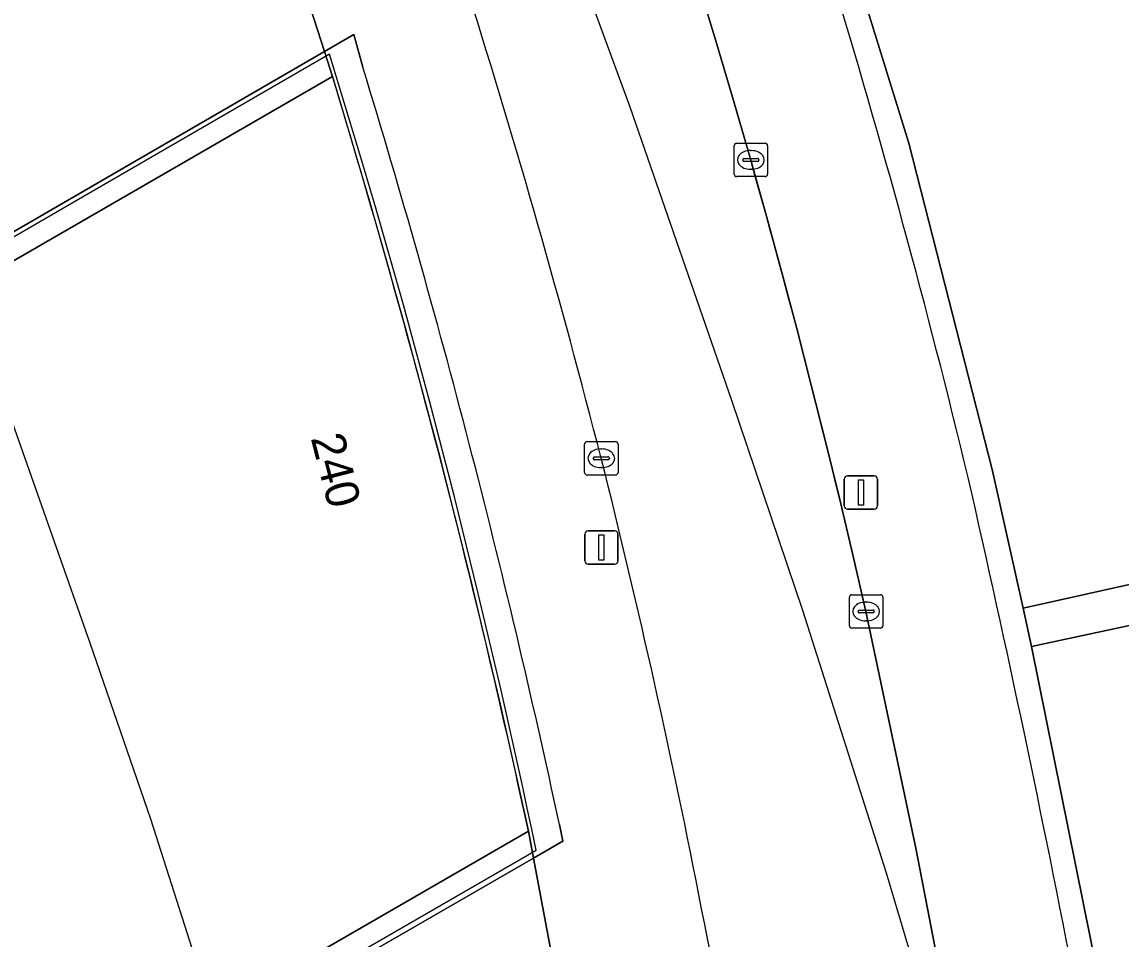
# Model space of a CAD drawing. Extents: x 155018 to 156648, y 383979 to 385733.
# Drawn here: x 156032.12 to 156065.01, y 384884.22 to 384911.65 of the extents above; entities that cross this region are included whole.
import ezdxf

# ---------------------------------------------------------------- set-up
doc = ezdxf.new("R2010")
doc.units = 0
for name, color, linetype in [('IMGEO_Berm_groen', 7, 'Continuous'), ('IMGEO_Dek', 7, 'Continuous'), ('IMGEO_Hek', 7, 'Continuous'), ('IMGEO_Kolk', 7, 'Continuous'), ('IMGEO_Lichtmast', 7, 'Continuous'), ('IMGEO_Lijnafwatering', 7, 'Continuous'), ('IMGEO_OVBaan_gesloten', 7, 'Continuous'), ('IMGEO_Pand', 7, 'Continuous'), ('IMGEO_Pand_nummerreeks', 7, 'Continuous'), ('IMGEO_Pand_overbouw', 7, 'Continuous'), ('IMGEO_Voetpad_gesloten', 7, 'Continuous'), ('IMGEO_Voetpad_op_trap', 7, 'Continuous'), ('IMGEO_Voetpad_open', 7, 'Continuous')]:
    doc.layers.add(name, color=color, linetype=linetype)

msp = doc.modelspace()

# ---------------------------------------------------------------- linework, layer by layer
at = {"layer": 'IMGEO_Berm_groen'}
msp.add_lwpolyline([(156048.02, 384938.183), (156051.936, 384928.479), (156055.886, 384916.978), (156058.656, 384908.023), (156061.157, 384898.221), (156062.08, 384894.114), (156067.946, 384895.427), (156068.244, 384894.235), (156062.331, 384892.966), (156064.757, 384880.912), (156066.062, 384873.898), (156067.041, 384867.895), (156068.116, 384859.746), (156069.485, 384845.924)], dxfattribs=at)
at = {"layer": 'IMGEO_Dek'}
for points in [[(156069.485, 384845.924), (156068.116, 384859.746), (156067.041, 384867.895), (156066.062, 384873.898), (156064.757, 384880.912), (156062.331, 384892.966), (156062.08, 384894.114), (156061.157, 384898.221), (156058.656, 384908.023), (156055.886, 384916.978), (156051.936, 384928.479), (156048.02, 384938.183)], [(156033.68, 384930.916), (156034.6, 384928.685), (156035.502, 384926.446), (156036.386, 384924.2), (156037.253, 384921.947), (156038.102, 384919.688), (156039.932, 384914.604), (156041.169, 384910.762), (156041.409, 384910.017), (156042.517, 384906.291), (156043.573, 384902.55), (156044.577, 384898.794), (156045.528, 384895.025), (156046.426, 384891.242), (156047.271, 384887.448), (156047.423, 384886.642), (156048.221, 384882.392), (156049.145, 384877.06), (156051.553, 384863.161), (156052.777, 384853.511), (156053.449, 384846.337)]]:
    msp.add_lwpolyline(points, dxfattribs=at)
at = {"layer": 'IMGEO_Hek'}
for centre, radius, start, end in [((155804.106, 384836.212), 263.673, 13.559, 20.33305), ((155627.906, 384798.953), 443.726, 8.87476, 12.90185)]:
    msp.add_arc(centre, radius, start, end, dxfattribs=at)
at = {"layer": 'IMGEO_Kolk'}
for p, q in [((156053.428, 384907.096), (156053.428, 384907.948)), ((156053.503, 384908.022), (156054.355, 384908.022)), ((156053.916, 384907.802), (156053.941, 384907.802)), ((156054.429, 384907.948), (156054.429, 384907.096)), ((156053.687, 384907.516), (156053.687, 384907.528)), ((156054.125, 384907.479), (156053.727, 384907.479)), ((156053.73, 384907.565), (156054.128, 384907.565)), ((156054.171, 384907.528), (156054.171, 384907.516)), ((156053.939, 384907.242), (156053.914, 384907.242)), ((156054.355, 384907.022), (156053.503, 384907.022)), ((156048.953, 384898.173), (156048.953, 384899.025)), ((156049.028, 384899.099), (156049.88, 384899.099)), ((156049.441, 384898.879), (156049.466, 384898.879)), ((156049.954, 384899.025), (156049.954, 384898.173)), ((156049.212, 384898.593), (156049.212, 384898.605)), ((156049.65, 384898.556), (156049.252, 384898.556)), ((156049.255, 384898.642), (156049.653, 384898.642)), ((156049.696, 384898.605), (156049.696, 384898.593)), ((156049.464, 384898.319), (156049.439, 384898.319)), ((156049.88, 384898.099), (156049.028, 384898.099)), ((156056.878, 384893.592), (156056.878, 384894.444)), ((156056.953, 384894.518), (156057.805, 384894.518)), ((156057.366, 384894.298), (156057.391, 384894.298)), ((156057.879, 384894.444), (156057.879, 384893.592)), ((156057.137, 384894.012), (156057.137, 384894.024)), ((156057.575, 384893.975), (156057.177, 384893.975)), ((156057.18, 384894.061), (156057.578, 384894.061)), ((156057.621, 384894.024), (156057.621, 384894.012)), ((156057.389, 384893.738), (156057.364, 384893.738)), ((156057.805, 384893.518), (156056.953, 384893.518))]:
    msp.add_line(p, q, dxfattribs=at)
for points in [[(156053.428, 384907.096), (156053.428, 384907.948)], [(156053.503, 384908.022), (156054.355, 384908.022)], [(156054.429, 384907.948), (156054.429, 384907.096)], [(156054.355, 384907.022), (156053.503, 384907.022)], [(156048.953, 384898.173), (156048.953, 384899.025)], [(156049.028, 384899.099), (156049.88, 384899.099)], [(156049.954, 384899.025), (156049.954, 384898.173)], [(156049.88, 384898.099), (156049.028, 384898.099)], [(156056.878, 384893.592), (156056.878, 384894.444)], [(156056.953, 384894.518), (156057.805, 384894.518)], [(156057.879, 384894.444), (156057.879, 384893.592)], [(156057.805, 384893.518), (156056.953, 384893.518)]]:
    msp.add_lwpolyline(points, dxfattribs=at)
for centre, radius, start, end in [((156053.505, 384907.946), 0.0765, 91.552, 178.448), ((156053.505, 384907.946), 0.0765, 91.552, 178.448), ((156054.353, 384907.946), 0.0765, 1.552, 88.448), ((156054.353, 384907.946), 0.0765, 1.552, 88.448), ((156053.727, 384907.525), 0.0403, 85.8775, 175.7526), ((156053.724, 384907.515), 0.0366, 178.938, 274.7102), ((156054.128, 384907.522), 0.043, 264.8664, 352.4533), ((156054.132, 384907.527), 0.0386, 1.7309, 96.639), ((156053.505, 384907.098), 0.0765, 181.552, 268.448), ((156053.505, 384907.098), 0.0765, 181.552, 268.448), ((156054.353, 384907.098), 0.0765, 271.552, 358.448), ((156054.353, 384907.098), 0.0765, 271.552, 358.448), ((156049.03, 384899.023), 0.0765, 91.552, 178.448), ((156049.03, 384899.023), 0.0765, 91.552, 178.448), ((156049.878, 384899.023), 0.0765, 1.552, 88.448), ((156049.878, 384899.023), 0.0765, 1.552, 88.448), ((156049.252, 384898.602), 0.0403, 85.8775, 175.7526), ((156049.249, 384898.592), 0.0366, 178.938, 274.7102), ((156049.653, 384898.599), 0.043, 264.8664, 352.4533), ((156049.657, 384898.604), 0.0386, 1.7309, 96.639), ((156049.03, 384898.175), 0.0765, 181.552, 268.448), ((156049.03, 384898.175), 0.0765, 181.552, 268.448), ((156049.878, 384898.175), 0.0765, 271.552, 358.448), ((156049.878, 384898.175), 0.0765, 271.552, 358.448), ((156056.955, 384894.442), 0.0765, 91.552, 178.448), ((156056.955, 384894.442), 0.0765, 91.552, 178.448), ((156057.803, 384894.442), 0.0765, 1.552, 88.448), ((156057.803, 384894.442), 0.0765, 1.552, 88.448), ((156057.177, 384894.021), 0.0403, 85.8775, 175.7526), ((156057.174, 384894.011), 0.0366, 178.938, 274.7102), ((156057.578, 384894.018), 0.043, 264.8664, 352.4533), ((156057.582, 384894.023), 0.0386, 1.7309, 96.639), ((156056.955, 384893.594), 0.0765, 181.552, 268.448), ((156056.955, 384893.594), 0.0765, 181.552, 268.448), ((156057.803, 384893.594), 0.0765, 271.552, 358.448), ((156057.803, 384893.594), 0.0765, 271.552, 358.448)]:
    msp.add_arc(centre, radius, start, end, dxfattribs=at)
for centre, major_axis, ratio, start_param, end_param in [((156053.915, 384907.522), (-0.387, 0.002), 0.722429, 4.712389, 7.853982), ((156053.94, 384907.522), (-0.39, 0.002), 0.717154, 1.570796, 4.712389), ((156049.44, 384898.599), (-0.387, 0.002), 0.722429, 4.712389, 7.853982), ((156049.465, 384898.599), (-0.39, 0.002), 0.717154, 1.570796, 4.712389), ((156057.365, 384894.018), (-0.387, 0.002), 0.722429, 4.712389, 7.853982), ((156057.39, 384894.018), (-0.39, 0.002), 0.717154, 1.570796, 4.712389)]:
    msp.add_ellipse(centre, major_axis=major_axis, ratio=ratio, start_param=start_param, end_param=end_param, dxfattribs=at)
at = {"layer": 'IMGEO_Lichtmast'}
for p, q in [((156056.725, 384897.176), (156056.725, 384897.976)), ((156056.725, 384897.976), (156056.725, 384897.176)), ((156056.825, 384898.076), (156057.615, 384898.076)), ((156057.615, 384898.076), (156056.825, 384898.076)), ((156057.715, 384897.976), (156057.715, 384897.176)), ((156057.715, 384897.176), (156057.715, 384897.976)), ((156057.615, 384897.076), (156056.825, 384897.076)), ((156056.825, 384897.076), (156057.615, 384897.076)), ((156048.962, 384895.53), (156048.962, 384896.33)), ((156048.962, 384896.33), (156048.962, 384895.53)), ((156049.062, 384896.43), (156049.852, 384896.43)), ((156049.852, 384896.43), (156049.062, 384896.43)), ((156049.952, 384896.33), (156049.952, 384895.53)), ((156049.952, 384895.53), (156049.952, 384896.33)), ((156049.852, 384895.43), (156049.062, 384895.43)), ((156049.062, 384895.43), (156049.852, 384895.43))]:
    msp.add_line(p, q, dxfattribs=at)
for points in [[(156057.145, 384897.951), (156057.295, 384897.951), (156057.295, 384897.201), (156057.145, 384897.201), (156057.145, 384897.951)], [(156049.382, 384896.305), (156049.532, 384896.305), (156049.532, 384895.555), (156049.382, 384895.555), (156049.382, 384896.305)]]:
    msp.add_lwpolyline(points, dxfattribs=at)
for centre, start, end in [((156056.825, 384897.976), 90, 180), ((156056.825, 384897.976), 90, 180), ((156057.615, 384897.976), 0, 90), ((156057.615, 384897.976), 360, 90), ((156056.825, 384897.176), 180, 270), ((156056.825, 384897.176), 180, 270), ((156057.615, 384897.176), 270, 0), ((156057.615, 384897.176), 270, 0), ((156049.062, 384896.33), 90, 180), ((156049.062, 384896.33), 90, 180), ((156049.852, 384896.33), 0, 90), ((156049.852, 384896.33), 360, 90), ((156049.062, 384895.53), 180, 270), ((156049.062, 384895.53), 180, 270), ((156049.852, 384895.53), 270, 0), ((156049.852, 384895.53), 270, 0)]:
    msp.add_arc(centre, 0.1, start, end, dxfattribs=at)
at = {"layer": 'IMGEO_Lijnafwatering'}
for points in [[(156045.059, 384897.444), (156044.311, 384900.321), (156043.53, 384903.189), (156042.715, 384906.047), (156042.259, 384907.596), (156041.793, 384909.141), (156041.318, 384910.683), (156033.931, 384906.41)], [(156033.931, 384906.41), (156030.071, 384904.178), (156014.633, 384895.249)], [(156037.593, 384881.157), (156047.505, 384886.874), (156047.372, 384887.505), (156047.238, 384888.135), (156047.102, 384888.765), (156046.454, 384891.666), (156045.773, 384894.559), (156045.059, 384897.444)]]:
    msp.add_lwpolyline(points, dxfattribs=at)
at = {"layer": 'IMGEO_OVBaan_gesloten'}
for points in [[(156060.496, 384878.537), (156058.869, 384886.937), (156057.37, 384894.018), (156056.979, 384895.715), (156056.577, 384897.409), (156056.163, 384899.101), (156055.738, 384900.79), (156055.301, 384902.476), (156054.854, 384904.159), (156054.394, 384905.839), (156053.924, 384907.516), (156053.411, 384909.301), (156052.884, 384911.082), (156052.342, 384912.859), (156051.786, 384914.631), (156051.216, 384916.399), (156050.631, 384918.162), (156050.032, 384919.92), (156049.419, 384921.673), (156048.789, 384923.455), (156048.145, 384925.233), (156047.487, 384927.005), (156046.815, 384928.772), (156046.129, 384930.534)], [(156060.496, 384878.537), (156058.869, 384886.937), (156057.37, 384894.018)]]:
    msp.add_lwpolyline(points, dxfattribs=at)
for centre, radius, start, end in [((155832.964, 384844.998), 229.634, 15.79822, 19.5057), ((155789.737, 384831.978), 268.122, 14.38694, 17.48212), ((155789.737, 384831.978), 268.122, 14.38694, 17.48212), ((155805.27, 384836.847), 258.501, 12.77748, 15.86559), ((155805.555, 384837.135), 251.521, 10.99889, 14.14425), ((155805.555, 384837.135), 251.521, 10.99889, 14.14425), ((155605.291, 384794.657), 456.224, 9.51712, 11.43717), ((155605.291, 384794.657), 456.224, 9.51712, 11.43717)]:
    msp.add_arc(centre, radius, start, end, dxfattribs=at)
at = {"layer": 'IMGEO_Pand'}
msp.add_lwpolyline([(156041.409, 384910.017), (156019.378, 384897.297), (156015.467, 384895.04), (156007.252, 384890.298), (156008.617, 384887.934), (156003.544, 384885.006), (156002.181, 384887.356), (155996.821, 384884.308), (156007.97, 384864.757), (156047.271, 384887.448)], dxfattribs=at)
msp.add_arc((155775.793, 384828.981), 277.703, 12.1539, 16.96628, dxfattribs=at)
at = {"layer": 'IMGEO_Pand_overbouw'}
for points in [[(156067.752, 384846.961), (156066.212, 384854.951), (156065.601, 384858.12), (156061.663, 384873.134), (156060.081, 384879.164), (156057.992, 384886.194), (156055.482, 384894.048), (156053.363, 384900.328), (156050.321, 384909.105), (156048.279, 384914.644), (156046.647, 384918.9), (156044.351, 384924.676), (156043.087, 384927.641), (156041.379, 384931.534)], [(156019.077, 384930.797), (156020.968, 384926.754), (156022.558, 384923.198), (156024.194, 384919.469), (156025.317, 384916.836), (156027.472, 384911.414), (156029.011, 384907.398), (156030.938, 384902.172), (156034.148, 384893.08), (156035.96, 384887.818), (156037.993, 384881.487), (156039.75, 384875.68), (156040.562, 384872.8), (156042.005, 384867.554), (156043.013, 384863.814), (156044.557, 384857.338), (156045.458, 384853.556), (156048.022, 384841.099)]]:
    msp.add_lwpolyline(points, dxfattribs=at)
at = {"layer": 'IMGEO_Voetpad_gesloten'}
for points in [[(156069.485, 384845.924), (156068.116, 384859.746), (156067.041, 384867.895), (156066.062, 384873.898), (156064.757, 384880.912), (156062.331, 384892.966), (156062.08, 384894.114), (156061.157, 384898.221), (156058.656, 384908.023), (156055.886, 384916.978), (156051.936, 384928.479), (156048.02, 384938.183)], [(156069.485, 384845.924), (156068.116, 384859.746), (156067.041, 384867.895), (156066.062, 384873.898), (156064.757, 384880.912), (156062.331, 384892.966), (156062.08, 384894.114), (156061.157, 384898.221), (156058.656, 384908.023), (156055.886, 384916.978), (156051.936, 384928.479), (156048.02, 384938.183)], [(156046.129, 384930.534), (156046.815, 384928.772), (156047.487, 384927.005), (156048.145, 384925.233), (156048.789, 384923.455), (156049.419, 384921.673), (156050.032, 384919.92), (156050.631, 384918.162), (156051.216, 384916.399), (156051.786, 384914.631), (156052.342, 384912.859), (156052.884, 384911.082), (156053.411, 384909.301), (156053.924, 384907.516), (156054.394, 384905.839), (156054.854, 384904.159), (156055.301, 384902.476), (156055.738, 384900.79), (156056.163, 384899.101), (156056.577, 384897.409), (156056.979, 384895.715), (156057.37, 384894.018), (156058.869, 384886.937), (156060.496, 384878.537)], [(156039.002, 384920.023), (156039.21, 384919.439), (156038.367, 384918.952), (156039.932, 384914.604), (156041.169, 384910.762), (156042.048, 384911.271), (156042.318, 384910.295)], [(156038.102, 384919.688), (156039.932, 384914.604), (156041.169, 384910.762), (156041.409, 384910.017)], [(156042.318, 384910.295), (156042.048, 384911.271), (156041.169, 384910.762), (156041.409, 384910.017)], [(156057.37, 384894.018), (156058.869, 384886.937), (156060.496, 384878.537)], [(156047.271, 384887.448), (156047.423, 384886.642), (156048.304, 384887.15), (156048.2, 384887.647)], [(156047.271, 384887.448), (156047.423, 384886.642), (156048.221, 384882.392), (156049.145, 384877.06), (156051.553, 384863.161), (156052.777, 384853.511), (156053.449, 384846.337), (156054.04, 384836.955), (156053.536, 384836.048), (156052.897, 384834.623), (156052.641, 384833.49), (156052.458, 384832.066), (156052.473, 384831.694), (156052.513, 384830.695), (156052.769, 384829.362), (156053.189, 384828.12), (156053.664, 384827.078), (156054.339, 384826.12), (156054.337, 384819.179), (156058.291, 384820.442), (156059.02, 384820.675)], [(156048.2, 384887.647), (156048.304, 384887.15), (156047.423, 384886.642), (156048.221, 384882.392), (156049.145, 384877.06), (156051.553, 384863.161), (156052.777, 384853.511), (156053.449, 384846.337), (156054.04, 384836.955), (156053.536, 384836.048), (156052.897, 384834.623), (156052.641, 384833.49), (156052.458, 384832.066), (156052.473, 384831.694), (156052.513, 384830.695), (156052.769, 384829.362), (156053.189, 384828.12), (156053.664, 384827.078), (156054.339, 384826.12), (156054.337, 384819.179), (156058.291, 384820.442), (156059.02, 384820.675)]]:
    msp.add_lwpolyline(points, dxfattribs=at)
for points in [[(156041.169, 384910.762), (156039.932, 384914.604), (156038.367, 384918.952), (156015.169, 384905.56), (156019.469, 384898.196)], [(156049.145, 384877.06), (156048.221, 384882.392), (156047.423, 384886.642), (156023.283, 384872.722), (156027.099, 384866.034), (156027.634, 384865.095), (156047.842, 384876.336)]]:
    msp.add_lwpolyline(points, close=True, dxfattribs=at)
for centre, radius, start, end in [((155832.964, 384844.998), 229.634, 15.79822, 19.5057), ((155789.737, 384831.978), 268.122, 14.38694, 17.48212), ((155789.737, 384831.978), 268.122, 14.38694, 17.48212), ((155775.793, 384828.981), 277.703, 12.1539, 16.96628), ((155775.793, 384828.981), 277.703, 12.1539, 16.96628), ((155782.511, 384830.732), 271.716, 12.09103, 17.02669), ((155782.511, 384830.732), 271.716, 12.09103, 17.02669), ((155805.27, 384836.847), 258.501, 12.77748, 15.86559), ((155805.555, 384837.135), 251.521, 10.99889, 14.14425), ((155805.555, 384837.135), 251.521, 10.99889, 14.14425), ((155605.291, 384794.657), 456.224, 9.51712, 11.43717), ((155605.291, 384794.657), 456.224, 9.51712, 11.43717)]:
    msp.add_arc(centre, radius, start, end, dxfattribs=at)
at = {"layer": 'IMGEO_Voetpad_op_trap'}
msp.add_lwpolyline([(156068.244, 384894.235), (156067.946, 384895.427), (156062.08, 384894.114), (156062.331, 384892.966)], close=True, dxfattribs=at)
at = {"layer": 'IMGEO_Voetpad_open'}
for points in [[(156007.252, 384890.298), (156015.467, 384895.04), (156019.378, 384897.297), (156041.409, 384910.017), (156041.169, 384910.762), (156019.469, 384898.196), (156015.169, 384905.56), (156038.367, 384918.952), (156038.102, 384919.688), (156029.096, 384914.462), (156017.206, 384907.579), (156014.335, 384905.924), (156010.399, 384903.656), (156005.605, 384900.893)], [(156005.916, 384862.665), (156018.236, 384869.793), (156022.422, 384862.367), (156022.792, 384861.709), (156022.945, 384861.792), (156023.556, 384862.127), (156027.916, 384864.588), (156027.634, 384865.095), (156027.099, 384866.034), (156023.283, 384872.722), (156047.423, 384886.642), (156047.271, 384887.448), (156007.97, 384864.757)]]:
    msp.add_lwpolyline(points, dxfattribs=at)

# ---------------------------------------------------------------- texts
at = {"layer": 'IMGEO_Pand_nummerreeks'}
msp.add_text('240', height=1, rotation=284.3493, dxfattribs=at).set_placement((156040.756, 384899.208))

doc.saveas('drawing.dxf')
